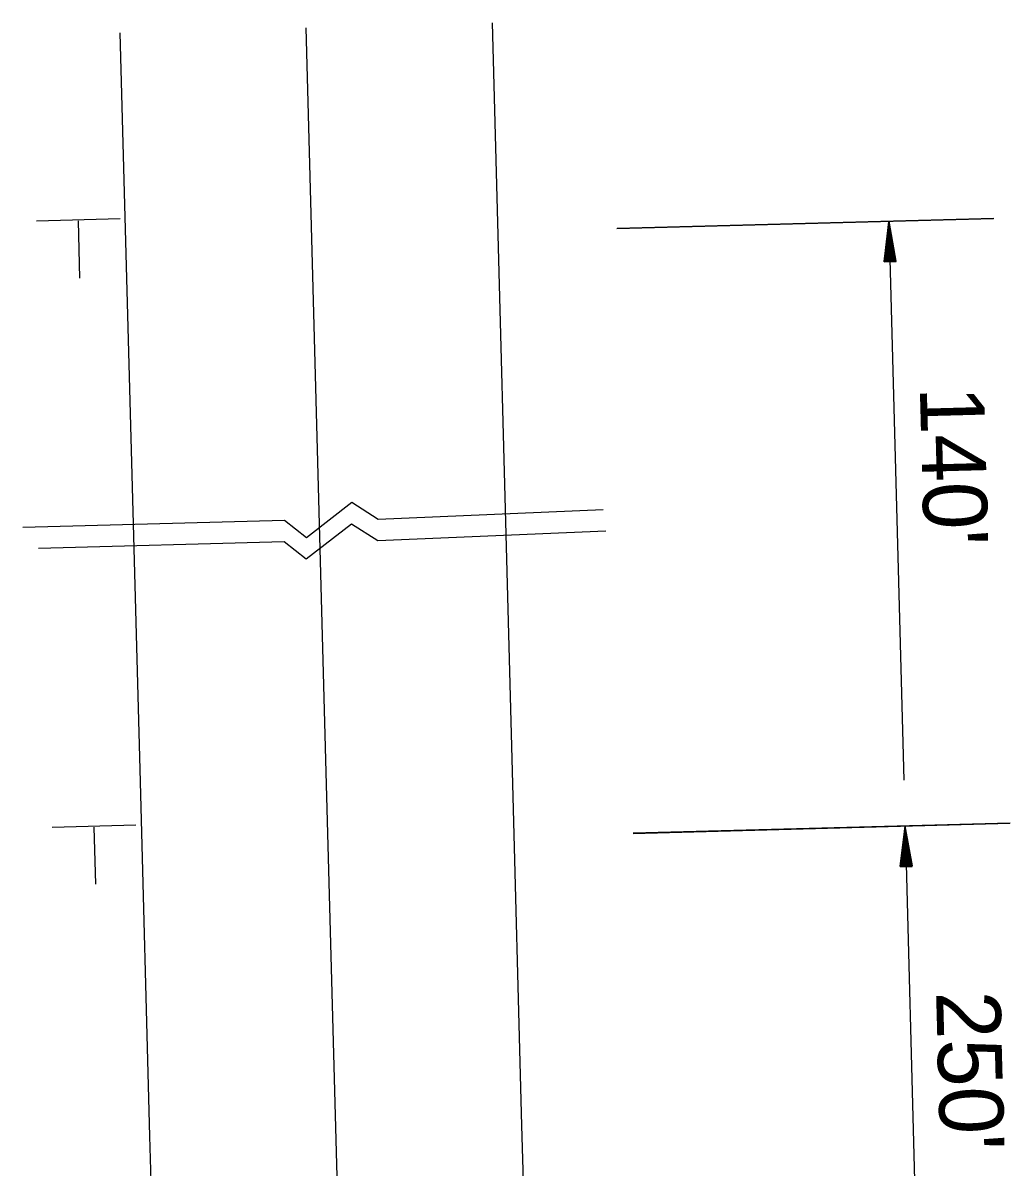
# Model space of a CAD drawing. Extents: x 1929624 to 1932072, y 596315 to 605954.
# Drawn here: x 1931312.7 to 1931405, y 597315.9 to 597422.8 of the extents above; entities that cross this region are included whole.
import ezdxf

# ---------------------------------------------------------------- set-up
doc = ezdxf.new("R2010")
doc.units = 0
doc.layers.add('Default', color=7, linetype='Continuous')

msp = doc.modelspace()

# ---------------------------------------------------------------- linework, layer by layer
at = {"layer": 'Default'}
for p, q in [((1931321.81, 597421.83), (1931323.66, 597353.02)), ((1931339.19, 597422.29), (1931341.06, 597352.78)), ((1931356.57, 597422.76), (1931358.42, 597354.01)), ((1931314.01, 597404.27), (1931321.83, 597404.48)), ((1931317.91, 597404.26), (1931318.05, 597398.92)), ((1931403.43, 597404.46), (1931368.24, 597403.51)), ((1931403.45, 597404.49), (1931368.26, 597403.55)), ((1931393.19, 597400.43), (1931393.65, 597404.19)), ((1931393.2, 597400.47), (1931393.67, 597404.23)), ((1931394.31, 597400.46), (1931393.65, 597404.19)), ((1931393.65, 597404.19), (1931395.05, 597352.02)), ((1931394.33, 597400.5), (1931393.67, 597404.23)), ((1931393.28, 597400.43), (1931393.66, 597403.57)), ((1931393.3, 597400.47), (1931393.68, 597403.61)), ((1931393.38, 597400.43), (1931393.68, 597402.92)), ((1931393.39, 597400.47), (1931393.7, 597402.96)), ((1931394.22, 597400.46), (1931393.66, 597403.57)), ((1931394.24, 597400.5), (1931393.68, 597403.61)), ((1931394.12, 597400.45), (1931393.68, 597402.92)), ((1931394.14, 597400.49), (1931393.7, 597402.96)), ((1931393.47, 597400.44), (1931393.7, 597402.3)), ((1931393.49, 597400.48), (1931393.72, 597402.34)), ((1931393.57, 597400.44), (1931393.72, 597401.66)), ((1931393.58, 597400.48), (1931393.73, 597401.7)), ((1931394.03, 597400.45), (1931393.7, 597402.3)), ((1931394.05, 597400.49), (1931393.72, 597402.34)), ((1931393.93, 597400.45), (1931393.72, 597401.66)), ((1931393.95, 597400.49), (1931393.73, 597401.7)), ((1931393.19, 597400.43), (1931394.31, 597400.46)), ((1931393.2, 597400.47), (1931394.33, 597400.5)), ((1931393.66, 597400.44), (1931393.73, 597401.04)), ((1931393.68, 597400.48), (1931393.75, 597401.07)), ((1931393.84, 597400.45), (1931393.73, 597401.04)), ((1931393.85, 597400.48), (1931393.75, 597401.07)), ((1931358.42, 597354.01), (1931359.34, 597319.77)), ((1931323.66, 597353.02), (1931324.58, 597318.78)), ((1931341.06, 597352.78), (1931342.1, 597313.86)), ((1931315.49, 597347.65), (1931323.31, 597347.86)), ((1931319.38, 597347.64), (1931319.52, 597342.3)), ((1931404.95, 597347.98), (1931369.75, 597347.03)), ((1931404.97, 597348.02), (1931369.77, 597347.07)), ((1931394.7, 597343.95), (1931395.16, 597347.72)), ((1931394.72, 597343.99), (1931395.18, 597347.75)), ((1931394.8, 597343.95), (1931395.18, 597347.09)), ((1931394.81, 597343.99), (1931395.2, 597347.13)), ((1931395.83, 597343.98), (1931395.16, 597347.72)), ((1931395.16, 597347.72), (1931396.56, 597295.55)), ((1931395.84, 597344.02), (1931395.18, 597347.75)), ((1931395.73, 597343.98), (1931395.18, 597347.09)), ((1931395.75, 597344.02), (1931395.2, 597347.13)), ((1931394.89, 597343.96), (1931395.2, 597346.44)), ((1931394.91, 597343.99), (1931395.22, 597346.48)), ((1931395.64, 597343.98), (1931395.2, 597346.44)), ((1931395.66, 597344.01), (1931395.22, 597346.48)), ((1931394.98, 597343.96), (1931395.21, 597345.82)), ((1931395, 597344), (1931395.23, 597345.86)), ((1931395.08, 597343.96), (1931395.23, 597345.19)), ((1931395.1, 597344), (1931395.25, 597345.22)), ((1931395.54, 597343.97), (1931395.21, 597345.82)), ((1931395.56, 597344.01), (1931395.23, 597345.86)), ((1931395.45, 597343.97), (1931395.23, 597345.19)), ((1931395.47, 597344.01), (1931395.25, 597345.22)), ((1931394.7, 597343.95), (1931395.83, 597343.98)), ((1931394.72, 597343.99), (1931395.84, 597344.02)), ((1931395.18, 597343.96), (1931395.25, 597344.56)), ((1931395.19, 597344), (1931395.27, 597344.6)), ((1931395.35, 597343.97), (1931395.25, 597344.56)), ((1931395.37, 597344.01), (1931395.27, 597344.6)), ((1931359.34, 597319.77), (1931361.12, 597253.18)), ((1931324.58, 597318.78), (1931326.37, 597252.24))]:
    msp.add_line(p, q, dxfattribs=at)
for points in [[(1931366.96, 597377.27), (1931345.94, 597376.39), (1931343.48, 597377.95), (1931339.24, 597374.67), (1931337.2, 597376.28), (1931312.75, 597375.63)], [(1931367.2, 597375.28), (1931345.91, 597374.39), (1931343.45, 597375.95), (1931339.21, 597372.67), (1931337.17, 597374.28), (1931314.21, 597373.67)]]:
    msp.add_lwpolyline(points, dxfattribs=at)

# ---------------------------------------------------------------- texts
for s, p in [("140'", (1931396.53, 597388.74)), ("250'", (1931398.05, 597332.26))]:
    msp.add_text(s, height=6, rotation=271.5377, dxfattribs=at).set_placement(p)

doc.saveas('drawing.dxf')
